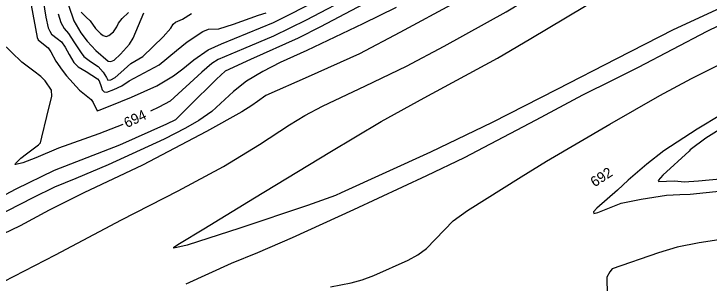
# Model space of a CAD drawing. Extents: x -291892836 to 2945206, y -477993085 to 1832792.
# Drawn here: x 1851914.3 to 1852187.4, y 544304.4 to 544410.1 of the extents above; entities that cross this region are included whole.
import ezdxf

# ---------------------------------------------------------------- set-up
doc = ezdxf.new("R2010")
doc.units = 0
doc.layers.add('DT_X_Contour_Minor', color=7, linetype='Continuous')
doc.layers.add('Level 19', color=7, linetype='Continuous')

msp = doc.modelspace()

# ---------------------------------------------------------------- linework, layer by layer
at = {"layer": 'DT_X_Contour_Minor'}
for points in [[(1852179.07, 544480.5), (1852178.63, 544480.26), (1852173.63, 544476.91), (1852170.76, 544474.68), (1852158.04, 544464.03), (1852144.72, 544452.9), (1852137.62, 544447.51), (1852130.7, 544442.89), (1852116.48, 544434.19), (1852101.45, 544424.2), (1852087.73, 544414.65), (1852065.88, 544402.81), (1852050.03, 544394.4), (1852029.83, 544385.46), (1852013.3, 544378.04), (1852009.94, 544375.8), (1852007.77, 544374.2), (1852003.8, 544371.69), (1851989.91, 544364.02), (1851964.86, 544350.72), (1851941.78, 544339.94), (1851928.19, 544333.1), (1851916.74, 544326.91), (1851899.75, 544318.77)], [(1852350.22, 544477.79), (1852347.62, 544476.01), (1852339.3, 544471.54), (1852325.12, 544464.63), (1852304.82, 544453.02), (1852296.64, 544449.08), (1852280.26, 544441.88), (1852269, 544437.49), (1852258.34, 544433.63), (1852233.66, 544423.37), (1852214.74, 544415.75), (1852195.44, 544407.58), (1852186.46, 544403.19), (1852159.5, 544389.06), (1852149.58, 544384.06), (1852137.68, 544378.2), (1852119.33, 544368.42), (1852091.12, 544353.6), (1852076.42, 544346.52), (1852047.75, 544333.26), (1852023.62, 544322.2), (1852009.94, 544316.36), (1851999.64, 544312.18), (1851981.85, 544303.98)], [(1851910.29, 544305.1), (1851930.59, 544315.55), (1851956.56, 544329.23), (1851978.79, 544340.7), (1851996.63, 544350.27), (1852010.77, 544358.91), (1852022.51, 544366.52), (1852028.6, 544370.18), (1852035.55, 544373.93), (1852052.37, 544381.9), (1852068.54, 544389.64), (1852083.32, 544397.5), (1852107.6, 544410.97), (1852114.64, 544415.07), (1852121.44, 544419.35), (1852128.85, 544424.5), (1852130.78, 544425.97)], [(1851925.13, 544419.53), (1851926.9, 544408.85), (1851927.83, 544404.67), (1851928.37, 544403.3), (1851929.12, 544402.21), (1851931.33, 544400.45), (1851932.95, 544399.21), (1851934.45, 544397.11), (1851936.06, 544394.25), (1851937.86, 544391.07), (1851939.56, 544389.32), (1851942.71, 544387.46), (1851947.18, 544384.68), (1851947.85, 544383.89), (1851948.57, 544381.62), (1851948.99, 544380.35), (1851949.71, 544379.53), (1851950.84, 544379.44), (1851953.61, 544380.46), (1851956.75, 544381.86), (1851959.6, 544383.88), (1851971.43, 544390.17), (1851978.21, 544395.81), (1851982.32, 544399.18), (1851988.58, 544403.26), (1851990.72, 544404.07), (1851994.81, 544404.25), (1852000.6, 544406.16), (1852010.43, 544409.59), (1852013.4, 544410.48)], [(1852058.87, 544417.88), (1852034.69, 544405.04), (1852026.02, 544400.62), (1852007.2, 544392.19), (1851997.25, 544387.66), (1851993.87, 544384.55), (1851983.05, 544373.8), (1851977.73, 544368.53), (1851974.19, 544366.78), (1851955.77, 544358.65), (1851930.13, 544348.61), (1851915.08, 544341.28), (1851902.57, 544334.8)], [(1851921.15, 544413.49), (1851923.45, 544400.92), (1851923.82, 544399.93), (1851925.22, 544398.73), (1851927.83, 544396.74), (1851928.78, 544395.26), (1851930.84, 544391.59), (1851933.22, 544387.98), (1851934.95, 544385.86), (1851940.02, 544380.23), (1851944.66, 544376.56), (1851945.5, 544375.32), (1851946.99, 544372.11), (1851948.17, 544372.51), (1851956.35, 544375.76), (1851960.54, 544377.4), (1851970.45, 544381.91), (1851977.03, 544385.79), (1851980.63, 544388.54), (1851984.93, 544392.09), (1851990.64, 544396), (1851995.84, 544398.39), (1852016.21, 544406.69), (1852034.7, 544416.16)], [(1852048.6, 544418.04), (1852029.1, 544407.65), (1852016.3, 544401.44), (1852004.44, 544396.39), (1851994.51, 544392.21), (1851992.08, 544390.6), (1851988.07, 544387.19), (1851975.72, 544375.82), (1851971.29, 544373.47), (1851967.96, 544371.88)], [(1852198.47, 544415.71), (1852173.22, 544403.84), (1852151.03, 544392.44), (1852127.61, 544380.39), (1852102.16, 544367.47), (1852077.92, 544355.89), (1852042.86, 544339.84), (1852040.65, 544338.88), (1852029.64, 544334.94), (1852003.01, 544325.95), (1851982.36, 544319.3), (1851977.07, 544318.12), (1851977.17, 544318.54), (1851979.34, 544320.03), (1851988.93, 544325.74), (1852008.76, 544337.87), (1852038.34, 544355.87), (1852058.61, 544367.88), (1852075.49, 544377.23), (1852104.32, 544392.76), (1852117.37, 544400.44), (1852145.22, 544417.24)], [(1851935.78, 544413.49), (1851937.86, 544407.44), (1851940.54, 544402.73), (1851943.03, 544399.44), (1851946.48, 544395.72), (1851951.31, 544391.56), (1851952.4, 544391.42), (1851953.63, 544391.99), (1851956.14, 544394.26), (1851959.73, 544398.2), (1851961.16, 544400.57), (1851965.3, 544410.58)], [(1852064.4, 544412.69), (1852051.39, 544406.17), (1852029.34, 544395.7), (1852018.95, 544391), (1852012.09, 544387.56), (1852005.67, 544383.71), (1852000.6, 544379.68), (1851992.02, 544371.82), (1851986.99, 544368.28), (1851981.75, 544365.22), (1851973.36, 544360.95), (1851951.28, 544350.88), (1851938.67, 544345.5), (1851930.25, 544342.07), (1851921.73, 544337.9), (1851896.55, 544325.13)], [(1851940.75, 544410.87), (1851942.72, 544408.89), (1851944.24, 544407.38), (1851946.4, 544404.38), (1851948.29, 544402.44), (1851949.4, 544401.64), (1851950.53, 544401.3), (1851951.61, 544401.6), (1851953.38, 544403.13), (1851954.73, 544405.02), (1851955.42, 544406.55), (1851956.88, 544408.26), (1851959.35, 544410.68)], [(1851931.7, 544410.15), (1851932.76, 544406.76), (1851934.02, 544404.43), (1851935.73, 544402.42), (1851937.84, 544399.15), (1851940.77, 544394.89), (1851941.83, 544393.41), (1851944.4, 544391.47), (1851947.37, 544389.42), (1851949.4, 544387.24), (1851950.62, 544385.2), (1851951.25, 544384.15), (1851952.32, 544384.29), (1851954.08, 544385.17), (1851956.26, 544387.12), (1851960.28, 544390.68), (1851964.89, 544393.37), (1851973, 544401.07), (1851976.01, 544404.46), (1851976.88, 544406.14), (1851977.82, 544406.86), (1851980.51, 544408.05), (1851984.04, 544410.31)], [(1851957.12, 544366.74), (1851947.64, 544363.06), (1851931.81, 544357.48), (1851922.88, 544353.67), (1851917.88, 544351.64), (1851915.12, 544350.94), (1851914.78, 544351.03), (1851914.96, 544351.43), (1851917.04, 544353.47), (1851919.21, 544355.22), (1851924, 544358.72), (1851924.74, 544359.53), (1851925.29, 544361.77), (1851927.26, 544369.8), (1851929.26, 544377.88), (1851929.1, 544380.16), (1851926.54, 544383.87), (1851924.94, 544385.59), (1851922.14, 544387.64), (1851917.38, 544391.13), (1851909.36, 544399.08)], [(1852038.63, 544303.02), (1852046.77, 544304.6), (1852051.09, 544305.76), (1852055.66, 544307.43), (1852069.11, 544313.43), (1852072.94, 544315.48), (1852076.33, 544317.98), (1852086.79, 544328.84), (1852092.41, 544332.88), (1852113.54, 544346.12), (1852123.52, 544352.34), (1852148.42, 544366.86), (1852168.01, 544378.04), (1852180.45, 544384.83), (1852190.98, 544389.99)], [(1852192.24, 544370.62), (1852182.73, 544364.87), (1852169.65, 544356.37), (1852162.88, 544351.1), (1852155.63, 544344.83), (1852151.43, 544340.91), (1852143.25, 544333.91), (1852142, 544332.43), (1852142.03, 544331.74), (1852143.66, 544332.1), (1852152.89, 544335.76), (1852160.63, 544337.37), (1852170.66, 544339.01), (1852175.84, 544339.27), (1852179.93, 544339.37), (1852205.05, 544342.01)], [(1852194.82, 544366.9), (1852186.08, 544361.34), (1852179.93, 544356.79), (1852179.56, 544356.26)], [(1852179.56, 544356.26), (1852169.22, 544346.87), (1852167.34, 544344.76), (1852167.6, 544344.31), (1852170.66, 544344.45), (1852173.97, 544344.64), (1852177.52, 544344.26), (1852183.2, 544344.57), (1852209.87, 544347.14)], [(1852405.9, 544298.18), (1852380.8, 544313.02), (1852360.84, 544323.5), (1852337.92, 544334.17), (1852334.38, 544334.55), (1852328.07, 544334.69), (1852309.76, 544334.41), (1852306.19, 544334.18), (1852302.08, 544333.65), (1852291.1, 544331.52), (1852276.75, 544328.63), (1852267.13, 544327.62), (1852240.46, 544325.89), (1852218.79, 544325.19), (1852208.22, 544324.08), (1852183.43, 544320.27), (1852174.78, 544318.54), (1852167.52, 544316.38), (1852149.28, 544310), (1852148.35, 544308.93), (1852147.23, 544306.71), (1852147.18, 544304.81), (1852147.59, 544295.56)]]:
    msp.add_lwpolyline(points, dxfattribs=at)

# ---------------------------------------------------------------- texts
at = {"layer": 'Level 19'}
for s, rotation, p in [('694', 25.3992, (1851958.7, 544365.26)), ('692', 33.0482, (1852142.41, 544341.99))]:
    msp.add_text(s, height=4, rotation=rotation, dxfattribs=at).set_placement(p)

doc.saveas('drawing.dxf')
